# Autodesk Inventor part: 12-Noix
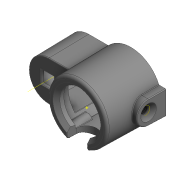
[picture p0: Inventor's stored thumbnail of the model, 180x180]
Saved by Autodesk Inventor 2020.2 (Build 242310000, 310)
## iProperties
Created: 2022-03
Part Number: 12-Noix
Material: Fonte, moulé
Document SubType Name: Modeling
Designer: %USERNAME%
Density: 7.15 g/cm^3
Appearance: Gris clair
Author: %USERNAME%
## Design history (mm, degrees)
sketch "Esquisse2"
  geometry: L1 (-15.984, 14.75)-(-30, 14.75); L2 (-30, -14.75)-(-15.984, -14.75); L3 (20.02, 8.5)-(25, 8.5); L4 (25, 8.5)-(25, -8.5); L5 (25, -8.5)-(20.02, -8.5); L6 (20.02, 8.5)-(20.02, -8.5); A1 r 21.75 centre (0, 0) between (-15.984, 14.75) and (-15.984, -14.75); A2 r 14.75 centre (-30, 0) between (-30, 14.75) and (-30, -14.75); 1 further point
  constraints: 12 end point, 7 point on circle, 3 parallel, 2 centre point, 2 horizontal, 2 perpendicular, 2 tangent, 1 coincident, 1 vertical
  dimensions: "d0" = 43.5 diameter of A1; "d1" = 29.5 distance between parallel lines of L2 L1; "d2" = 30 distance of point (0, 0) A2.centre; "d7" = 17 distance of L3.end L4.end; "d8" = 25 distance from line of L4 point (0, 0)
extrude "Extrusion1" new body sketch "Esquisse2" distance "d3" = 38.4; taper "d4" = 0 deg
extrude "Extrusion2" join sketch "Esquisse2" distance "d5" = 28.5; taper "d6" = 0 deg
extrude "Extrusion3" join sketch "Esquisse2" distance "d9" = 20.5; taper "d10" = 0 deg
feature "Dépouille de face3" dims angle "d14" = 1 deg
fillet "Congé2"
sketch "Esquisse3"
  geometry: L1 (30, -14.75)-(15.984, -14.75) reference; L2 (15.984, 14.75)-(30, 14.75) reference; L3 (-25, 8.5)-(-20.02, 8.5) reference; L4 (-25, -8.5)-(-25, 8.5) reference; L5 (-20.02, -8.5)-(-25, -8.5) reference; L6 (13.748, 12.75)-(30, 12.75); L7 (30, -12.75)-(13.748, -12.75); L8 (8.906, -16.5)-(-8.906, -16.5); L9 (8.906, 16.5)-(-8.906, 16.5); L10 (-18, -5.25)-(-18, 5.25); A1 r 21.75 centre (0, 0) between (-20.02, -8.5) and (15.984, -14.75) reference; A2 r 14.75 centre (30, 0) between (30, -14.75) and (30, 14.75) reference; A3 r 21.75 centre (0, 0) between (15.984, 14.75) and (-20.02, 8.5) reference; A4 r 18.75 centre (0, 0) between (-17.685, -6.23) and (13.748, 12.75); A5 r 18.75 centre (0, 0) between (13.748, 12.75) and (-17.685, -6.23); A6 r 12.75 centre (30, 0) between (30, -12.75) and (30, 12.75); 1 further point
  constraints: 13 point on circle, 10 end point, 3 centre point, 2 parallel, 1 horizontal, 1 perpendicular, 2 other
  dimensions: "d17" = 3 radial gap between concentric circles of A4 A1; "d18" = 2 radial gap between concentric circles of A6 A2; "d19" = 7 distance between parallel lines of L4 L10; "d20" = 33 distance between parallel lines of L9 L8
  node "Boucle projetée1"
extrude "Extrusion4" cut sketch "Esquisse3" distance "d21" = 32.5; taper "d22" = 0 deg
extrude "Extrusion5" cut sketch "Esquisse3" distance "d23" = 26.3; taper "d24" = 0 deg
feature "Dépouille de face4" dims angle "d25" = 1 deg
fillet "Congé3" dims "d15" = 2, "d16" = 0.5
sketch "Esquisse4"
  geometry: L1 (0, 0)-(0, 44.888); L2 (0, 16.2)-(-8.42, 16.2); L3 (-19.114, 38.4)-(19.114, 38.4) reference; L4 (17.138, 38.4)-(14.65, 35.912); L5 (18.183, 32.5)-(8.876, 32.5) reference; L6 (17.138, 38.4)-(0, 38.4); L7 (15.267, 32.5)-(0, 32.5); L8 (0, 38.4)-(0, 32.5); A1 r 15.3 centre (0, 31.5) between (0, 16.2) and (14.65, 35.912); A2 r 15.3 centre (0, 31.5) between (15.267, 32.5) and (14.65, 35.912)
  constraints: 12 end point, 5 point on circle, 5 point on line, 2 centre point, 1 coincident, 1 collinear, 1 horizontal, 1 midpoint, 1 perpendicular, 1 tangent, 1 vertical
  dimensions: "d26" = 30.6 diameter of A1; "d27" = 16.2 distance from line of L1.start L2; "d28" = 29.3 diameter of L4.end L1; "d29" = 45 deg angle of L4 L3
revolve "Révolution1" sketch "Esquisse4" stored, may be unused: angle "d30" = 90 deg
sketch "Esquisse5"
  geometry: L1 (-35.6, -4.6)-(-26.4, -4.6); L2 (-26.4, -4.6)-(-26.4, 4.6); L3 (-26.4, 4.6)-(-35.6, 4.6); L4 (-35.6, 4.6)-(-35.6, -4.6); L5 (-35.6, -4.6)-(-26.4, 4.6); L6 (-26.4, -4.6)-(-35.6, 4.6); 3 further points
  constraints: 12 end point, 3 midpoint, 2 parallel, 2 perpendicular, 1 horizontal, 1 horizontal alignment
  dimensions: "d31" = 31 distance of point (0, 0) point (-31, 0); "d32" = 9.2 distance of L1.start L1.end
extrude "Extrusion6" cut sketch "Esquisse5" extent not by distance; stored distance "d33" = 26.3; taper "d34" = 0 deg
sketch "Esquisse6"
  geometry: L1 (-17.138, 38.4)-(17.138, 38.4) reference; L2 (7.1, 38.4)-(7.1, 31.4); L3 (-7.1, 31.4)-(-7.1, 38.4); A1 r 7.1 centre (0, 31.4) between (-7.1, 31.4) and (7.1, 31.4); 2 further points
  constraints: 4 end point, 2 point on circle, 2 point on line, 2 tangent, 1 centre point, 1 midpoint, 1 perpendicular, 1 vertical, 1 vertical alignment
  dimensions: "d35" = 14.2 distance between parallel lines of L3 L2; "d36" = 7 distance from line of L1 A1.centre
extrude "Extrusion7" cut sketch "Esquisse6" extent not by distance; stored distance "d37" = 21.191; taper "d38" = 0 deg
node "Plan de construction1"
sketch "Esquisse7"
  geometry: L1 (16.052, 14.404)-(30, 14.404) reference; L2 (30, -14.404)-(16.052, -14.404) reference; L3 (-21.609, -3.333)-(-24.162, -3.333) reference; L4 (-24.654, -1.791)-(-24.654, 1.791) reference; L5 (-24.162, 3.333)-(-21.609, 3.333) reference; L6 (30, 12.404)-(13.815, 12.404) reference; L7 (8.69, 16.154)-(-8.69, 16.154) reference; L8 (-17.654, 5.128)-(-17.654, -5.128) reference; L9 (-8.69, -16.154)-(8.69, -16.154) reference; L10 (13.815, -12.404)-(30, -12.404) reference; L11 (-7.1, -15.933)-(-7.1, -13.516) reference; A1 r 21.404 centre (0, 0) between (-20.965, -4.317) and (15.685, -14.564) reference; A2 r 14.404 centre (30, 0) between (30, -14.404) and (30, 14.404) reference; A3 r 21.404 centre (0, 0) between (15.685, 14.564) and (-20.965, 4.317) reference; A4 r 12.404 centre (30, 0) between (30, -12.404) and (30, 12.404) reference; A5 r 18.404 centre (0, 0) between (13.45, 12.563) and (8.932, 16.092) reference; A6 r 18.404 centre (0, 0) between (-8.932, 16.092) and (-17.633, 5.271) reference; A7 r 18.404 centre (0, 0) between (-17.633, -5.271) and (-8.932, -16.092) reference; A8 r 18.404 centre (0, 0) between (8.932, -16.092) and (13.45, -12.563) reference; A9 r 4.5 centre (-11.032, -18.342) between (-7.1, -16.154) and (-12.006, -13.949); A10 r 4.5 centre (11.032, -18.342) between (12.006, -13.949) and (7.1, -16.154); 1 further point
  constraints: 8 point on circle, 3 point on line, 2 centre point, 1 equal radius, 1 horizontal alignment, 14 other
  dimensions: "d41" = 4.5 radius of A9
extrude "Extrusion8" join sketch "Esquisse7" stored distance "d42" = 10; taper "d43" = 0 deg
node "Plan de construction2"
sketch "Esquisse8"
  geometry: A1 r 7.786 centre (8.5, -12.223) between (0.716, -12.359) and (16.284, -12.359) reference; 2 further points
  constraints: 1 coincident
hole "Perçage1" sketch "Esquisse8" at (8.5, -12.223) diameter "d45" = 4.917; stored, may be unused: countersink angle "d49" = 90 deg, drill point angle "d51" = 118 deg; dims "d46" = 12, "d47" = 11.5, "d48" = 2, "d50" = 17.1
fillet "Congé4" dims "d39" = 0.5
node "Point de construction1"
node "Axe de construction1"
sketch "Esquisse9"
  geometry: L1 (-17.419, 15.223)-(-22.705, 15.223); L2 (-21.709, 9.765)-(-21.709, 14.682) reference; L3 (-21.709, 12.223)-(-15.308, 12.223); 1 further point
  constraints: 4 end point, 2 horizontal, 1 midpoint
  dimensions: "d52" = 6 diameter of L1 L3
feature "SrfRévolution1" sketch "Esquisse9" dims angle "d53" = 270 deg
node "Solide1"
body "Srf1"
node "Projeter les arêtes coupées1"
other parameters: "d40" = 12.7, "d44" = 90 deg
